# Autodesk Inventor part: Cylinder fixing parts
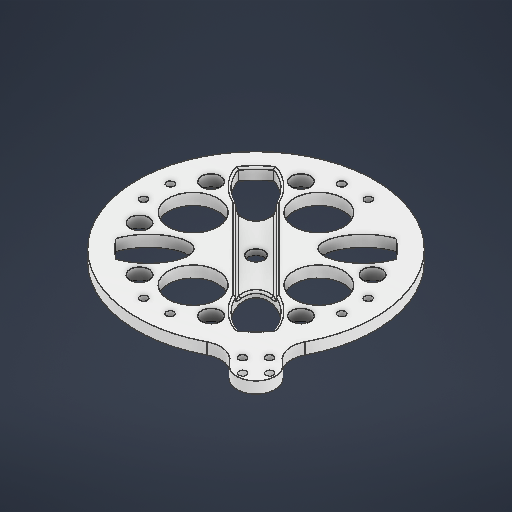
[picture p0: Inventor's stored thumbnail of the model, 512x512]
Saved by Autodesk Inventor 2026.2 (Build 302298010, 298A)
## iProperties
Created: 2026-05
Part Number: Cylinder fixing parts
Material: ABS 플라스틱
Document SubType Name: Modeling
Designer: work
Density: 1.06 g/cm^3
Appearance: 매끄러움 - 흰색
Author: work
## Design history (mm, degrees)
sketch "스케치1"
  geometry: L1 (-15, 60)-(15, 60); L2 (15, 60)-(15, -60); L3 (15, -60)-(-15, -60); L4 (-15, -60)-(-15, 60); L5 (-15, 60)-(15, -60); L6 (15, 60)-(-15, -60); L7 (-7, 52)-(7, 52); L8 (7, 52)-(7, -52); L9 (7, -52)-(-7, -52); L10 (-7, -52)-(-7, 52); L11 (-7, 52)-(7, -52); L12 (7, 52)-(-7, -52); L13 (31, -10)-(0, -10); L14 (0, -10)-(0, 10); L15 (0, 10)-(31, 10); L16 (31, 10)-(31, -10); L17 (25, 5)-(25, -5); L18 (31, 0)-(0, 0); L19 (25, 5)-(15, 5); L20 (15, 5)-(15, -5); L21 (15, -5)-(25, -5); L22 (25, -5)-(25, 5); C1 r 4.25 at (0, 0); C2 r 2 at (7, -52); C3 r 2 at (-7, -52); C4 r 2 at (7, 52); C5 r 2 at (-7, 52); C6 r 2 at (25, 5); C7 r 2 at (25, -5); C8 r 2 at (15, 5); C9 r 2 at (15, -5); 4 further points
  constraints: 44 end point, 9 centre point, 9 coincident, 8 parallel, 7 midpoint, 5 horizontal, 4 perpendicular, 1 point on line, 1 vertical
  dimensions: "d0" = 8.5 diameter of C1; "d1" = 120 distance of L1.end L2.end; "d2" = 30 distance of L1.start L1.end; "d3" = 8 distance between parallel lines of L1 L7; "d4" = 4 diameter of C2; "d5" = 4 diameter of C3; "d6" = 4 diameter of C4; "d7" = 4 diameter of C5; "d8" = 8 distance between parallel lines of L2 L8; "d9" = 16 distance between parallel lines of L2 L16; "d10" = 20 distance of L15.end L13.start; "d11" = 6 distance between parallel lines of L16 L17; "d13" = 4 diameter of C6; "d14" = 4 diameter of C7; "d15" = 10 distance of L17.start L17.end; "d16" = 4 diameter of C8; "d17" = 4 diameter of C9; "d18" = 10 distance between parallel lines of L22 L20
extrude "돌출1" new body sketch "스케치1" distance "d19" = 6; taper "d20" = 0 deg
sketch "스케치2"
  geometry: L1 (30.147, 7)-(-8, 7); L2 (-8, 7)-(-8, -7); L3 (-8, -7)-(30.147, -7); L4 (30.147, -7)-(30.147, 7); L5 (-8, 0)-(30.147, 0); 1 further point
  constraints: 10 end point, 2 midpoint, 2 parallel, 1 horizontal, 1 perpendicular, 1 point on line
  dimensions: "d21" = 8 distance from line of L2 point (0, 0); "d22" = 14 distance between parallel lines of L3 L1
extrude "돌출2" cut sketch "스케치2" distance "d23" = 3; taper "d24" = 0 deg
fillet "모깎기1" dims "d25" = 8
chamfer "모따기1" distance "d26" = 1; stored, may be unused: second distance "d27" = 2, angle "d28" = 45 deg
chamfer "모따기2" distance "d29" = 0.25; stored, may be unused: second distance "d30" = 2, angle "d31" = 45 deg
chamfer "모따기3" distance "d32" = 0.5; stored, may be unused: second distance "d33" = 2, angle "d34" = 45 deg
sketch "스케치3"
  geometry: L1 (-6.5, 24)-(6.5, 24); L2 (6.5, 24)-(6.5, 0); L3 (6.5, 0)-(-6.5, 0); L4 (-6.5, 0)-(-6.5, 24); L5 (-15, -60)-(-15, -15) reference; L6 (15, -60)-(-15, -60) reference; L7 (15, -15)-(15, -60) reference; L8 (60, -15)-(15, -15) reference; L9 (60, 15)-(60, -15) reference; L10 (15, 15)-(60, 15) reference; L11 (15, 60)-(15, 15) reference; L12 (-15, 60)-(15, 60) reference; L13 (-15, 15)-(-15, 60) reference; L14 (-60, 15)-(-15, 15) reference; L15 (-60, -15)-(-60, 15) reference; L16 (-15, -15)-(-60, -15) reference; C1 r 2 at (-52, 7) reference; C2 r 2 at (-52, -7) reference; C3 r 4.25 at (0, 0) reference; C4 r 2 at (52, 7) reference; C5 r 2 at (52, -7) reference; C6 r 2 at (-7, -52) reference; C7 r 2 at (7, -52) reference; C8 r 2 at (-7, 52) reference; C9 r 2 at (7, 52) reference; C10 r 62.5 at (0, 0); 5 further points
  constraints: 8 end point, 3 coincident, 2 parallel, 1 centre point, 1 horizontal, 1 midpoint, 1 perpendicular, 3 other
  dimensions: "d38" = 13 distance between parallel lines of L2 L4; "d39" = 24 distance between parallel lines of L3 L1; "d40" = 125 diameter of C10
extrude "돌출3" join sketch "스케치3" stored distance "d41" = 10; taper "d42" = 0 deg
sketch "스케치4" dims "d44" = 30, "d45" = 5
  geometry: L1 (-52, -7)-(-52, 7); L2 (-46, -7)-(-46, 7); L3 (-58, 7)-(-58, -7); L4 (0, 0)-(-52, 0); L5 (0, 0)-(0, -52); L6 (7, -46)-(-7, -46); L7 (7, -52)-(-7, -52); L8 (-7, -58)-(7, -58); L9 (0, 0)-(52, 0); L10 (46, 7)-(46, -7); L11 (52, 7)-(52, -7); L12 (58, -7)-(58, 7); L13 (0, 0)-(0, 52); L14 (-7, 46)-(7, 46); L15 (-7, 52)-(7, 52); L16 (7, 58)-(-7, 58); L17 (0, 0)-(-44.194, 44.194); L18 (-28.284, 28.284)-(-33, 0); L19 (-28.284, 28.284)-(0, 33); C1 r 4.25 at (0, 0) reference; C2 r 2 at (52, -7) reference; C3 r 2 at (52, 7) reference; C4 r 2 at (-52, 7) reference; C5 r 2 at (-52, -7) reference; C6 r 2 at (-7, 52) reference; C7 r 2 at (7, 52) reference; C8 r 2 at (-7, -52) reference; C9 r 2 at (7, -52) reference; C10 r 13 at (0, -33); C11 r 13 at (33, 0); C12 r 5 at (-42.384, 18.787); C13 r 5 at (-18.787, 42.384); C14 r 5 at (-42.384, -18.787); C15 r 5 at (-18.787, -42.384); C16 r 5 at (18.787, -42.384); C17 r 5 at (42.384, -18.787); C18 r 5 at (42.384, 18.787); C19 r 5 at (18.787, 42.384); A1 r 6 centre (-52, -7) between (-58, -7) and (-46, -7); A2 r 6 centre (-52, 7) between (-46, 7) and (-58, 7); A3 r 6 centre (7, -52) between (7, -58) and (7, -46); A4 r 6 centre (-7, -52) between (-7, -46) and (-7, -58); A5 r 6 centre (52, 7) between (58, 7) and (46, 7); A6 r 6 centre (52, -7) between (46, -7) and (58, -7); A7 r 6 centre (-7, 52) between (-7, 58) and (-7, 46); A8 r 6 centre (7, 52) between (7, 46) and (7, 58); 29 further points
  constraints: 46 end point, 18 centre point, 16 point on circle, 11 point on line, 4 coincident, 4 tangent, 2 vertical, 1 horizontal, 1 midpoint, 1 parallel, 1 symmetric about line, 135 other
  dimensions: "d43" = 12 diameter of A2; "d48" = 360 deg dimension on L4.start L18.end (derived); "d50" = 45 deg angle of L4 L17; "d51" = 40 distance of L18.start point (0, 0); "d52" = 8 distance of point (-16.263, 16.263) point (-10.607, 10.607); "d53" = 5 distance of point (-30.862, 12.823) point (-30.04, 17.755); "d54" = 5 distance of point (-17.755, 30.04) point (-12.823, 30.862); "d55" = 3 dimension on C12; "d56" = 17 distance of L18.start C12.centre; "d57" = 10 diameter of C12; "d60" = 360 deg dimension on L4.start L18.start (derived)
extrude "돌출4" cut sketch "스케치4" distance "d62" = 10; taper "d63" = 0 deg
sketch "스케치5" dims "d68" = 20
  geometry: L1 (0, 0)-(53.033, -53.033); L2 (0, 0)-(62.5, 0); L3 (53.033, -45.962)-(45.962, -53.033); L4 (45.962, -53.033)-(53.033, -60.104); L5 (53.033, -60.104)-(60.104, -53.033); L6 (60.104, -53.033)-(53.033, -45.962); L7 (53.033, -45.962)-(53.033, -60.104); L8 (45.962, -53.033)-(60.104, -53.033); C1 r 2 at (45.962, -53.033); C2 r 2 at (53.033, -60.104); C3 r 2 at (53.033, -45.962); C4 r 2 at (60.104, -53.033); A1 r 62.5 centre (0, 0) between (62.5, 0) and (29.419, -55.143) reference; A2 r 12 centre (35.067, -65.731) between (44.867, -58.805) and (29.419, -55.143); A3 r 12 centre (65.731, -35.067) between (55.143, -29.419) and (58.805, -44.867); 3 further points
  constraints: 16 end point, 6 centre point, 6 point on circle, 5 symmetric about line, 3 coincident, 3 parallel, 2 midpoint, 1 horizontal, 1 perpendicular, 1 tangent, 7 other
  dimensions: "d64" = 45 deg angle of L1 L2; "d65" = 10 distance of L3.start L3.end; "d66" = 10 distance of L4.end L3.end; "d67" = 75 distance of L1.start L1.end; "d69" = 4 diameter of C1; "d70" = 4 diameter of C2; "d71" = 12 radius of A2
extrude "돌출5" join sketch "스케치5" stored distance "d72" = 10; taper "d73" = 0 deg
sketch "스케치6"
  geometry: L1 (26.517, -15.91)-(15.91, -26.517); L2 (15.91, -26.517)-(-26.517, 15.91); L3 (-26.517, 15.91)-(-15.91, 26.517); L4 (-15.91, 26.517)-(26.517, -15.91); L5 (26.517, -15.91)-(-26.517, 15.91); L6 (15.91, -26.517)-(-15.91, 26.517); L7 (26.517, -15.91)-(41.517, -15.91); L8 (5.303, 5.303)-(-5.303, -5.303); 1 further point
  constraints: 16 end point, 4 midpoint, 2 parallel, 1 equal length, 1 horizontal, 1 perpendicular
  dimensions: "d74" = 15 distance of L1.start L1.end; "d75" = 135 deg angle of L1 L7; "d76" = 60 distance of L1.end L2.end
extrude "돌출6" cut sketch "스케치6" distance "d77" = 3; taper "d78" = 0 deg
fillet "모깎기2" dims "d79" = 1
fillet "모깎기3" dims "d80" = 1
node "솔리드1"
pattern_circular "원형 패턴1" dims angle "d36" = 360 deg
node "투영된 루프1"
node "투영된 루프2"
node "스케치 - 원형 패턴1" dims "d48" = 360 deg (derived)
node "스케치 - 원형 패턴2" dims "d60" = 360 deg (derived)
